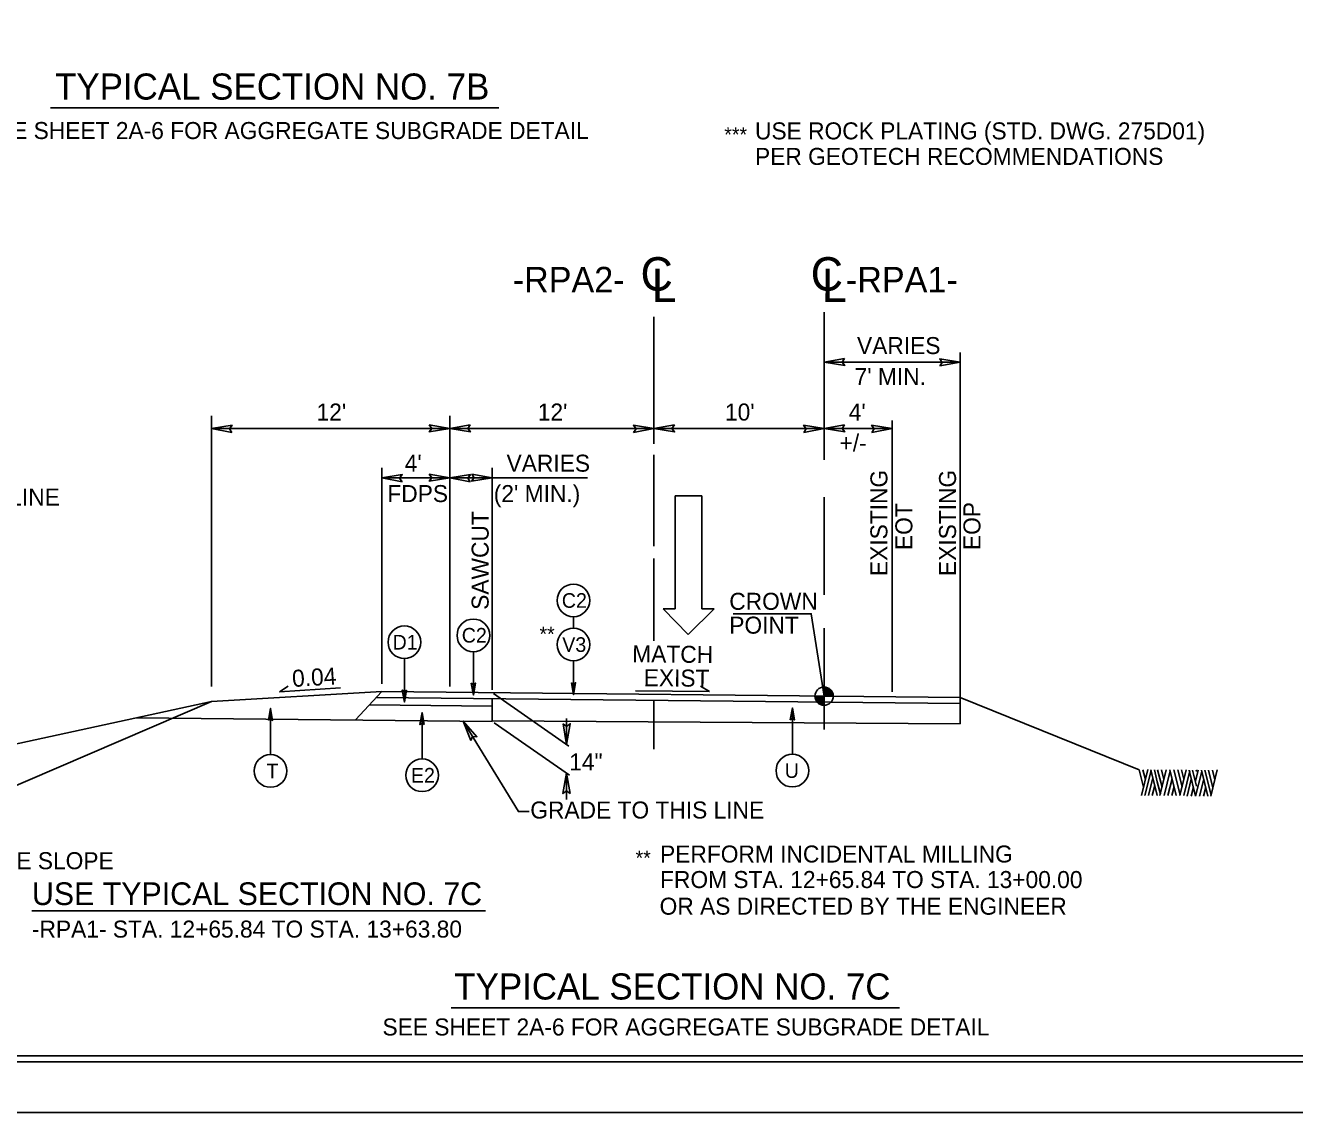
# Model space of a CAD drawing. Extents: x 573748 to 574632, y -54663 to -53209.
# Drawn here: x 574045 to 574156.8, y -54133.7 to -54037.8 of the extents above; entities that cross this region are included whole.
import ezdxf

# ---------------------------------------------------------------- set-up
doc = ezdxf.new("R2010")
doc.units = 0
for name, color, linetype in [('Prop Dimension', 7, 'Continuous'), ('Prop Dimension Text', 7, 'Continuous'), ('Prop Lane Arrow CELL', 7, 'Continuous'), ('Prop Terminator CELL', 7, 'Continuous'), ('Sheet Cutting Line CELL', 7, 'Continuous'), ('Sheet Plot Border Inside CELL', 7, 'Continuous'), ('Sheet Plot Border Outside CELL', 7, 'Continuous'), ('Sheet Typical CELL', 7, 'Continuous'), ('Typical Arrow Superelevation CELL', 7, 'Continuous'), ('Typical Grade Point Symbol CELL', 7, 'Continuous'), ('Typical Hinge Slope Arterial CELL', 7, 'Continuous'), ('Typical ID Circle CELL', 7, 'Continuous'), ('Typical Pavement Slope CELL', 7, 'Continuous'), ('Typical Terminator CELL', 7, 'Continuous'), ('Typical Text Centerline CELL', 7, 'Continuous'), ('Typical Text General CELL', 7, 'Continuous'), ('Typical Text ID Circle CELL', 7, 'Continuous'), ('Typical Text Label CELL', 7, 'Continuous')]:
    doc.layers.add(name, color=color, linetype=linetype)

# ---------------------------------------------------------------- blocks, each defined once
blk = doc.blocks.new('CENTERLINE TEXT CL')
at = {"layer": 'Typical Text Centerline CELL'}
blk.add_text('C', height=1.64, dxfattribs=at).set_placement((-0.546, -0.261))
blk.add_text('L', height=1.641, rotation=359.9469, dxfattribs=at).set_placement((-0.001, -0.821))

msp = doc.modelspace()

# ---------------------------------------------------------------- linework, layer by layer
at = {"layer": 'Prop Dimension'}
for p, q in [((574100.36, -54074.69), (574100.36, -54063.5)), ((574115.36, -54076.12), (574115.36, -54063.08)), ((574127.36, -54097.07), (574127.36, -54066.65)), ((574115.36, -54067.51), (574127.36, -54067.51)), ((574061.36, -54096.11), (574061.36, -54072.23)), ((574082.36, -54096.11), (574082.36, -54072.23)), ((574121.36, -54096.56), (574121.36, -54072.66)), ((574082.36, -54073.36), (574061.36, -54073.36)), ((574082.36, -54073.36), (574100.36, -54073.36)), ((574100.36, -54073.36), (574115.36, -54073.36)), ((574115.36, -54073.36), (574121.36, -54073.36)), ((574100.36, -54083.74), (574100.36, -54075.67)), ((574076.36, -54095.86), (574076.36, -54076.82)), ((574086.1, -54096.4), (574086.1, -54076.82)), ((574082.36, -54077.71), (574076.36, -54077.71)), ((574094.5, -54077.71), (574082.36, -54077.71)), ((574115.36, -54088.02), (574115.36, -54079.4)), ((574100.36, -54092.08), (574100.36, -54084.8)), ((574115.36, -54099.88), (574115.36, -54090.97)), ((574086.21, -54096.72), (574092.87, -54101.35)), ((574100.36, -54101.63), (574100.36, -54097.29)), ((574127.36, -54099.39), (574127.36, -54097.07)), ((574127.36, -54097.07), (574143.13, -54103.44)), ((574127.36, -54099.39), (574086.1, -54099.12)), ((574086.27, -54099.29), (574092.91, -54103.91)), ((574092.66, -54098.93), (574092.66, -54101.2)), ((574092.66, -54103.73), (574092.66, -54106.06)), ((574143.51, -54104.99), (574143.13, -54103.44)), ((574143.33, -54105.72), (574143.89, -54103.42)), ((574143.68, -54104.3), (574143.47, -54103.44)), ((574143.63, -54105.72), (574144.18, -54103.51)), ((574144.73, -54105.72), (574144.16, -54103.44)), ((574144.73, -54104.5), (574144.47, -54103.44)), ((574145.15, -54104.97), (574144.76, -54103.44)), ((574144.96, -54105.72), (574145.52, -54103.44)), ((574145.31, -54104.31), (574145.1, -54103.44)), ((574145.33, -54105.72), (574145.87, -54103.54)), ((574146.4, -54105.72), (574145.84, -54103.44)), ((574146.74, -54105.65), (574146.19, -54103.44)), ((574146.91, -54104.95), (574146.54, -54103.44)), ((574146.72, -54105.72), (574147.29, -54103.44)), ((574147.07, -54104.28), (574146.87, -54103.44)), ((574147.06, -54105.72), (574147.6, -54103.55)), ((574148.1, -54105.76), (574147.53, -54103.47)), ((574148.18, -54104.9), (574147.83, -54103.47)), ((574148.1, -54104.44), (574148.34, -54103.47)), ((574148.11, -54105.76), (574148.65, -54103.59)), ((574148.18, -54103.58), (574148.16, -54103.47)), ((574148.23, -54103.54), (574148.2, -54103.44)), ((574149.19, -54105.76), (574148.62, -54103.47)), ((574149.47, -54105.68), (574148.92, -54103.47)), ((574149.63, -54105.03), (574149.25, -54103.47)), ((574149.45, -54105.76), (574150.02, -54103.46)), ((574149.8, -54104.34), (574149.59, -54103.47)), ((574143.96, -54105.72), (574144.34, -54104.16)), ((574144.28, -54105.72), (574144.5, -54104.82)), ((574145, -54105.58), (574144.73, -54104.5)), ((574145.67, -54105.72), (574146.04, -54104.24)), ((574146.02, -54105.72), (574146.21, -54104.93)), ((574147.37, -54105.76), (574147.73, -54104.27)), ((574147.72, -54105.76), (574147.91, -54104.99)), ((574148.12, -54104.31), (574148.1, -54104.22)), ((574148.46, -54105.76), (574148.82, -54104.27)), ((574148.81, -54105.76), (574149, -54104.99))]:
    msp.add_line(p, q, dxfattribs=at)
for points in [[(574107.33, -54089.69), (574114.22, -54089.69), (574115.36, -54096.95)], [(574089.37, -54107.13), (574088.41, -54107.13), (574083.55, -54099.15)]]:
    msp.add_lwpolyline(points, dxfattribs=at)
at = {"layer": 'Prop Lane Arrow CELL'}
for p, q in [((574102.24, -54079.29), (574102.24, -54089.26)), ((574104.59, -54079.29), (574102.24, -54079.29)), ((574104.59, -54089.26), (574104.59, -54079.29)), ((574102.24, -54089.26), (574101.17, -54089.26)), ((574101.17, -54089.26), (574103.38, -54091.51)), ((574103.38, -54091.51), (574105.66, -54089.26)), ((574105.66, -54089.26), (574104.59, -54089.26))]:
    msp.add_line(p, q, dxfattribs=at)
at = {"layer": 'Prop Terminator CELL'}
for points in [[(574117.16, -54067.17), (574115.36, -54067.51), (574117.18, -54067.8), (574116.94, -54067.49)], [(574125.56, -54067.84), (574127.36, -54067.51), (574125.55, -54067.21), (574125.78, -54067.53)], [(574063.16, -54073.69), (574061.36, -54073.36), (574063.18, -54073.06), (574062.94, -54073.38)], [(574080.56, -54073.03), (574082.36, -54073.36), (574080.55, -54073.66), (574080.78, -54073.34)], [(574084.16, -54073.03), (574082.36, -54073.36), (574084.18, -54073.66), (574083.94, -54073.34)], [(574098.56, -54073.69), (574100.36, -54073.36), (574098.55, -54073.06), (574098.78, -54073.38)], [(574102.16, -54073.03), (574100.36, -54073.36), (574102.18, -54073.66), (574101.94, -54073.34)], [(574113.56, -54073.69), (574115.36, -54073.36), (574113.55, -54073.06), (574113.78, -54073.38)], [(574117.16, -54073.03), (574115.36, -54073.36), (574117.18, -54073.66), (574116.94, -54073.34)], [(574119.56, -54073.69), (574121.36, -54073.36), (574119.55, -54073.06), (574119.78, -54073.38)], [(574078.16, -54078.04), (574076.36, -54077.71), (574078.18, -54077.41), (574077.94, -54077.73)], [(574080.56, -54077.37), (574082.36, -54077.71), (574080.55, -54078), (574080.78, -54077.69)], [(574084.16, -54078.04), (574082.36, -54077.71), (574084.18, -54077.41), (574083.94, -54077.73)], [(574084.31, -54077.37), (574086.1, -54077.71), (574084.29, -54078), (574084.52, -54077.69)], [(574084.22, -54100.85), (574083.55, -54099.15), (574084.76, -54100.53), (574084.37, -54100.5)], [(574092.35, -54099.4), (574092.66, -54101.2), (574092.98, -54099.39), (574092.66, -54099.62)], [(574092.97, -54105.53), (574092.66, -54103.73), (574092.34, -54105.54), (574092.66, -54105.31)]]:
    msp.add_lwpolyline(points, close=True, dxfattribs=at)
at = {"layer": 'Sheet Cutting Line CELL'}
msp.add_line((573944.17, -54133.67), (574280.97, -54133.67), dxfattribs=at)
at = {"layer": 'Sheet Plot Border Inside CELL'}
msp.add_lwpolyline([(574280.07, -53918.16), (573946.77, -53918.16), (573946.77, -54129.18), (574280.07, -54129.18)], close=True, dxfattribs=at)
at = {"layer": 'Sheet Plot Border Outside CELL'}
msp.add_lwpolyline([(574280.97, -53913.67), (573944.17, -53913.67), (573944.17, -54133.67), (574280.97, -54133.67)], close=True, dxfattribs=at)
at = {"layer": 'Sheet Typical CELL'}
msp.add_lwpolyline([(574277.57, -53918.67), (573977.57, -53918.67), (573977.57, -54128.67), (574277.57, -54128.67)], close=True, dxfattribs=at)
at = {"layer": 'Typical Arrow Superelevation CELL'}
for p, q in [((574067.35, -54096.57), (574068.11, -54096.06)), ((574067.35, -54096.57), (574072.74, -54096.23)), ((574105.26, -54096.54), (574104.47, -54096.07)), ((574105.26, -54096.54), (574098.73, -54096.47))]:
    msp.add_line(p, q, dxfattribs=at)
at = {"layer": 'Typical Grade Point Symbol CELL'}
for p, q in [((574115.36, -54096.95), (574115.36, -54096.14)), ((574114.56, -54096.95), (574115.36, -54096.95)), ((574116.17, -54096.95), (574115.36, -54096.95)), ((574115.36, -54097.75), (574115.36, -54096.95)), ((574115.36, -54096.95), (574115.36, -54097.75))]:
    msp.add_line(p, q, dxfattribs=at)
for points in [[(574115.37, -54096.14), (574115.37, -54096.14), (574115.37, -54096.95)], [(574115.38, -54096.14), (574115.38, -54096.95)], [(574115.4, -54096.14), (574115.4, -54096.95)], [(574115.42, -54096.14), (574115.42, -54096.95)], [(574115.43, -54096.14), (574115.43, -54096.95)], [(574115.45, -54096.15), (574115.45, -54096.95)], [(574115.46, -54096.15), (574115.46, -54096.95)], [(574115.48, -54096.15), (574115.48, -54096.95)], [(574115.5, -54096.15), (574115.5, -54096.95)], [(574115.51, -54096.15), (574115.51, -54096.95)], [(574115.53, -54096.16), (574115.53, -54096.95)], [(574115.55, -54096.16), (574115.55, -54096.95)], [(574115.56, -54096.17), (574115.56, -54096.95)], [(574115.58, -54096.17), (574115.58, -54096.95)], [(574115.59, -54096.17), (574115.59, -54096.95)], [(574115.61, -54096.18), (574115.61, -54096.95)], [(574115.63, -54096.19), (574115.63, -54096.95)], [(574115.64, -54096.19), (574115.64, -54096.95)], [(574115.66, -54096.2), (574115.66, -54096.95)], [(574115.67, -54096.21), (574115.67, -54096.95)], [(574115.69, -54096.21), (574115.69, -54096.95)], [(574115.71, -54096.22), (574115.71, -54096.95)], [(574115.72, -54096.23), (574115.72, -54096.95)], [(574115.74, -54096.24), (574115.74, -54096.95)], [(574115.75, -54096.24), (574115.75, -54096.95)], [(574115.77, -54096.25), (574115.77, -54096.95)], [(574115.79, -54096.26), (574115.79, -54096.95)], [(574114.56, -54096.95), (574114.56, -54097.03)], [(574114.57, -54096.95), (574114.57, -54097.13)], [(574114.59, -54096.95), (574114.59, -54097.19)], [(574114.61, -54096.95), (574114.61, -54097.23)], [(574114.62, -54096.95), (574114.62, -54097.27)], [(574114.64, -54096.95), (574114.64, -54097.31)], [(574114.66, -54096.95), (574114.66, -54097.34)], [(574114.67, -54096.95), (574114.67, -54097.37)], [(574114.69, -54096.95), (574114.69, -54097.39)], [(574114.7, -54096.95), (574114.7, -54097.41)], [(574114.72, -54096.95), (574114.72, -54097.44)], [(574114.74, -54096.95), (574114.74, -54097.45)], [(574114.75, -54096.95), (574114.75, -54097.47)], [(574114.77, -54096.95), (574114.77, -54097.49)], [(574114.78, -54096.95), (574114.78, -54097.51)], [(574114.8, -54096.95), (574114.8, -54097.53)], [(574114.82, -54096.95), (574114.82, -54097.54)], [(574114.83, -54096.95), (574114.83, -54097.56)], [(574114.85, -54096.95), (574114.85, -54097.57)], [(574114.86, -54096.95), (574114.86, -54097.58)], [(574114.88, -54096.95), (574114.88, -54097.59)], [(574114.9, -54096.95), (574114.9, -54097.61)], [(574114.91, -54096.95), (574114.91, -54097.62)], [(574114.93, -54096.95), (574114.93, -54097.63)], [(574114.95, -54096.95), (574114.95, -54097.64)], [(574114.96, -54096.95), (574114.96, -54097.65)], [(574114.98, -54096.95), (574114.98, -54097.66)], [(574114.99, -54096.95), (574114.99, -54097.66)], [(574115.01, -54096.95), (574115.01, -54097.67)], [(574115.03, -54096.95), (574115.03, -54097.68)], [(574115.04, -54096.95), (574115.04, -54097.69)], [(574115.06, -54096.95), (574115.06, -54097.69)], [(574115.07, -54096.95), (574115.07, -54097.7)], [(574115.09, -54096.95), (574115.09, -54097.71)], [(574115.11, -54096.95), (574115.11, -54097.71)], [(574115.12, -54096.95), (574115.12, -54097.72)], [(574115.14, -54096.95), (574115.14, -54097.72)], [(574115.15, -54096.95), (574115.15, -54097.73)], [(574115.17, -54096.95), (574115.17, -54097.73)], [(574115.19, -54096.95), (574115.19, -54097.73)], [(574115.2, -54096.95), (574115.2, -54097.74)], [(574115.22, -54096.95), (574115.22, -54097.74)], [(574115.24, -54096.95), (574115.24, -54097.74)], [(574115.25, -54096.95), (574115.25, -54097.74)], [(574115.27, -54096.95), (574115.27, -54097.75)], [(574115.28, -54096.95), (574115.28, -54097.75)], [(574115.3, -54096.95), (574115.3, -54097.75)], [(574115.32, -54096.95), (574115.32, -54097.75)], [(574115.33, -54096.95), (574115.33, -54097.75)], [(574115.35, -54096.95), (574115.35, -54097.75), (574115.35, -54097.75)], [(574115.8, -54096.27), (574115.8, -54096.95)], [(574115.82, -54096.28), (574115.82, -54096.95)], [(574115.84, -54096.3), (574115.84, -54096.95)], [(574115.85, -54096.31), (574115.85, -54096.95)], [(574115.87, -54096.32), (574115.87, -54096.95)], [(574115.88, -54096.33), (574115.88, -54096.95)], [(574115.9, -54096.35), (574115.9, -54096.95)], [(574115.92, -54096.36), (574115.92, -54096.95)], [(574115.93, -54096.38), (574115.93, -54096.95)], [(574115.95, -54096.39), (574115.95, -54096.95)], [(574115.96, -54096.41), (574115.96, -54096.95)], [(574115.98, -54096.43), (574115.98, -54096.95)], [(574116, -54096.45), (574116, -54096.95)], [(574116.01, -54096.47), (574116.01, -54096.95)], [(574116.03, -54096.5), (574116.03, -54096.95)], [(574116.04, -54096.52), (574116.04, -54096.95)], [(574116.06, -54096.55), (574116.06, -54096.95)], [(574116.08, -54096.58), (574116.08, -54096.95)], [(574116.09, -54096.61), (574116.09, -54096.95)], [(574116.11, -54096.65), (574116.11, -54096.95)], [(574116.13, -54096.69), (574116.13, -54096.95)], [(574116.14, -54096.75), (574116.14, -54096.95)], [(574116.16, -54096.83), (574116.16, -54096.95)]]:
    msp.add_lwpolyline(points, dxfattribs=at)
msp.add_circle((574115.36, -54096.95), 0.806, dxfattribs=at)
for start, end in [(359.9905, 89.9905), (179.9905, 269.9905)]:
    msp.add_arc((574115.36, -54096.95), 0.806, start, end, dxfattribs=at)
at = {"layer": 'Typical Hinge Slope Arterial CELL'}
for q in [(574027.94, -54104.68), (574030.3, -54110.78)]:
    msp.add_line((574061.36, -54097.41), q, dxfattribs=at)
at = {"layer": 'Typical ID Circle CELL'}
for p, q in [((574093.26, -54089.96), (574093.26, -54090.96)), ((574078.36, -54093.64), (574078.36, -54097.47)), ((574084.44, -54093.03), (574084.44, -54096.86)), ((574093.26, -54093.85), (574093.26, -54096.83)), ((574066.56, -54102.11), (574066.56, -54098.03)), ((574079.92, -54102.49), (574079.92, -54098.4)), ((574112.56, -54102.07), (574112.56, -54097.99))]:
    msp.add_line(p, q, dxfattribs=at)
for centre in [(574093.26, -54088.51), (574084.44, -54091.59), (574078.36, -54092.2), (574093.26, -54092.4), (574066.56, -54103.55), (574079.92, -54103.93), (574112.56, -54103.52)]:
    msp.add_circle(centre, 1.44, dxfattribs=at)
at = {"layer": 'Typical Pavement Slope CELL'}
for p, q in [((574076.36, -54096.54), (574061.36, -54097.41)), ((574074.06, -54099.05), (574076.36, -54096.54)), ((574127.36, -54097.6), (574075.88, -54097.07)), ((574127.36, -54097.07), (574076.36, -54096.54)), ((574086.1, -54099.18), (574086.1, -54097.17)), ((574086.1, -54097.84), (574075.28, -54097.73)), ((574086.1, -54099.18), (574054.74, -54098.85))]:
    msp.add_line(p, q, dxfattribs=at)
at = {"layer": 'Typical Terminator CELL'}
for points in [[(574084.26, -54095.8), (574084.44, -54096.86), (574084.63, -54095.8), (574084.44, -54095.93)], [(574093.08, -54095.78), (574093.26, -54096.83), (574093.45, -54095.77), (574093.26, -54095.91)], [(574078.54, -54096.41), (574078.36, -54097.47), (574078.18, -54096.41), (574078.36, -54096.54)], [(574066.37, -54099.08), (574066.56, -54098.03), (574066.74, -54099.09), (574066.56, -54098.95)], [(574080.1, -54099.46), (574079.92, -54098.4), (574079.73, -54099.46), (574079.92, -54099.33)], [(574112.38, -54099.04), (574112.56, -54097.99), (574112.75, -54099.05), (574112.56, -54098.92)]]:
    msp.add_lwpolyline(points, close=True, dxfattribs=at)
at = {"layer": 'Typical Text General CELL'}
msp.add_line((574045.53, -54115.87), (574085.52, -54115.87), dxfattribs=at)
at = {"layer": 'Typical Text Label CELL'}
for p, q in [((574047.17, -54045.07), (574086.68, -54045.07)), ((574082.49, -54124.42), (574122, -54124.42))]:
    msp.add_line(p, q, dxfattribs=at)

# ---------------------------------------------------------------- block references
at = {"layer": 'Prop Dimension', "xscale": 1.8000000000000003, "yscale": 1.8000000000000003}
for p in [(574100.16, -54060.73), (574115.16, -54060.73)]:
    msp.add_blockref('CENTERLINE TEXT CL', p, dxfattribs=at)

# ---------------------------------------------------------------- texts
at = {"layer": 'Prop Dimension'}
for s, height, p in [('-RPA2-', 2.25, (574087.91, -54061.35)), ('GRADE TO THIS LINE', 1.5, (574027.37, -54080.15)), ('GRADE TO THIS LINE', 1.5, (574089.46, -54107.74))]:
    msp.add_text(s, height=height, dxfattribs=at).set_placement(p)
at = {"layer": 'Prop Dimension Text'}
for s, height, p in [('TYPICAL SECTION NO. 7B', 2.3, (574047.57, -54044.35)), ('-RPA1-', 2.25, (574117.28, -54061.35)), ('VARIES', 1.5, (574118.26, -54066.79)), ("7' MIN.", 1.5, (574118.05, -54069.52)), ("12'", 1.5, (574070.62, -54072.65)), ("12'", 1.5, (574090.12, -54072.65)), ("10'", 1.5, (574106.62, -54072.65)), ("4'", 1.5, (574117.53, -54072.65)), ('+/-', 1.5, (574116.72, -54075.37)), ("4'", 1.5, (574078.39, -54077.16)), ('VARIES', 1.5, (574087.37, -54077.16)), ('FDPS', 1.5, (574076.86, -54079.84)), ("(2' MIN.)", 1.5, (574086.24, -54079.84)), ('CROWN', 1.5, (574107, -54089.34)), ('POINT', 1.5, (574107, -54091.44)), ('14"', 1.5, (574092.89, -54103.5)), ('TYPICAL SECTION NO. 7C', 2.3, (574082.76, -54123.7))]:
    msp.add_text(s, height=height, dxfattribs=at).set_placement(p)
for s, rotation, p in [('EXISTING', 90, (574120.94, -54086.36)), ('EXISTING', 90, (574126.99, -54086.36)), ('EOT', 90, (574123.14, -54084.07)), ('EOP', 90, (574129.14, -54084.07)), ('SAWCUT', 90, (574085.79, -54089.34)), ('MATCH', 359.4026, (574098.44, -54093.96)), ('0.04', 3.5612, (574068.51, -54096.15)), ('EXIST', 359.4026, (574099.45, -54096.07))]:
    msp.add_text(s, height=1.5, rotation=rotation, dxfattribs=at).set_placement(p)
at = {"layer": 'Typical Text General CELL'}
for s, height, p in [('SEE SHEET 2A-6 FOR AGGREGATE SUBGRADE DETAIL', 1.5, (574041.11, -54047.83)), ('USE ROCK PLATING (STD. DWG. 275D01)', 1.5, (574109.27, -54047.86)), ('PER GEOTECH RECOMMENDATIONS', 1.5, (574109.27, -54050.11)), ('VARIABLE SLOPE', 1.5, (574035.68, -54112.21)), ('PERFORM INCIDENTAL MILLING', 1.5, (574100.9, -54111.62)), ('FROM STA. 12+65.84 TO STA. 13+00.00', 1.5, (574100.9, -54113.87)), ('USE TYPICAL SECTION NO. 7C', 2, (574045.53, -54115.37)), ('OR AS DIRECTED BY THE ENGINEER', 1.5, (574100.86, -54116.22)), ('-RPA1- STA. 12+65.84 TO STA. 13+63.80', 1.5, (574045.53, -54118.24)), ('SEE SHEET 2A-6 FOR AGGREGATE SUBGRADE DETAIL', 1.5, (574076.43, -54126.87))]:
    msp.add_text(s, height=height, dxfattribs=at).set_placement(p)
at = {"layer": 'Typical Text ID Circle CELL'}
for s, height, p in [('***', 1.291, (574106.56, -54048.08)), ('C2', 1.291, (574092.24, -54089.16)), ('D1', 1.291, (574077.32, -54092.84)), ('C2', 1.291, (574083.42, -54092.23)), ('**', 1.291, (574090.27, -54092.12)), ('V3', 1.291, (574092.28, -54093.05)), ('T', 1.29, (574066.2, -54104.19)), ('U', 1.29, (574111.89, -54104.16)), ('E2', 1.291, (574078.94, -54104.57)), ('**', 1.291, (574098.74, -54111.86))]:
    msp.add_text(s, height=height, dxfattribs=at).set_placement(p)

doc.saveas('drawing.dxf')
